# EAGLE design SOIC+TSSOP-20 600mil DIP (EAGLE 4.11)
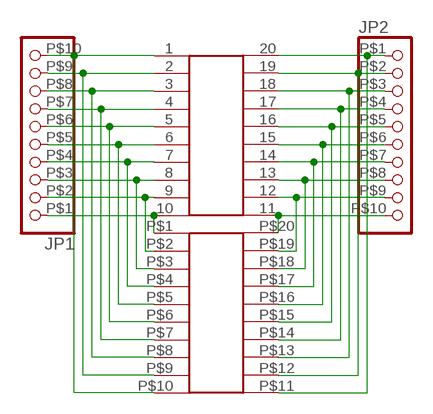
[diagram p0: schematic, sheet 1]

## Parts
JP1  PINHD-1X10THIN  [HEADER1X10]
JP2  PINHD-1X10THIN  [HEADER1X10]
U$1  SMD-20TSSOP  [TSSOP-20NM]
U$2  SMD-20SOIC  [SO-20NMW]

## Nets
N$1: JP1.P$10 U$1.1 U$2.P$10
N$2: JP1.P$9 U$1.2 U$2.P$9
N$3: JP1.P$8 U$1.3 U$2.P$8
N$4: JP1.P$7 U$1.4 U$2.P$7
N$5: JP1.P$6 U$1.5 U$2.P$6
N$6: JP1.P$5 U$1.6 U$2.P$5
N$7: JP1.P$4 U$1.7 U$2.P$4
N$8: JP1.P$3 U$1.8 U$2.P$3
N$9: JP1.P$2 U$1.9 U$2.P$2
N$10: JP1.P$1 U$1.10 U$2.P$1
N$11: JP2.P$1 U$1.20 U$2.P$11
N$12: JP2.P$2 U$1.19 U$2.P$12
N$13: JP2.P$3 U$1.18 U$2.P$13
N$14: JP2.P$5 U$1.16 U$2.P$15
N$15: JP2.P$4 U$1.17 U$2.P$14
N$16: JP2.P$6 U$1.15 U$2.P$16
N$17: JP2.P$7 U$1.14 U$2.P$17
N$18: JP2.P$8 U$1.13 U$2.P$18
N$19: JP2.P$9 U$1.12 U$2.P$19
N$20: JP2.P$10 U$1.11 U$2.P$20

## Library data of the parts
JP1 JP2 = boogie:PINHD-1X10: PIN HEADER
U$1 U$2 = boogie:SMD-20

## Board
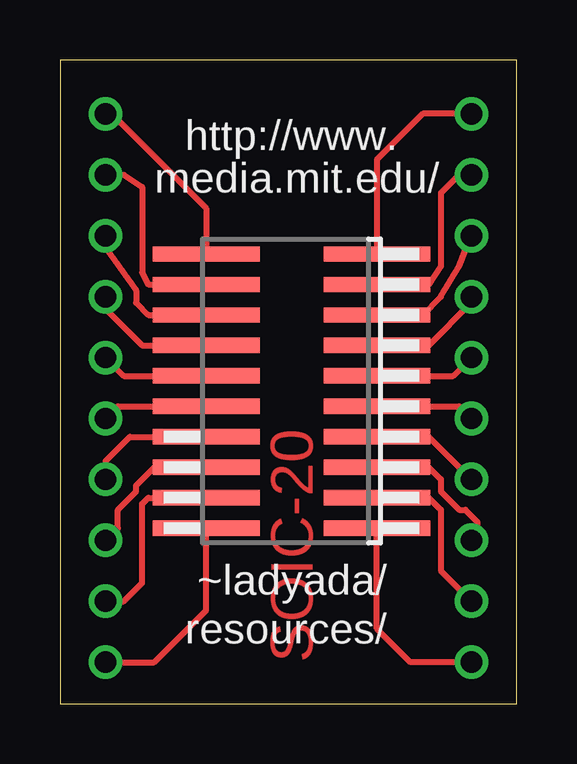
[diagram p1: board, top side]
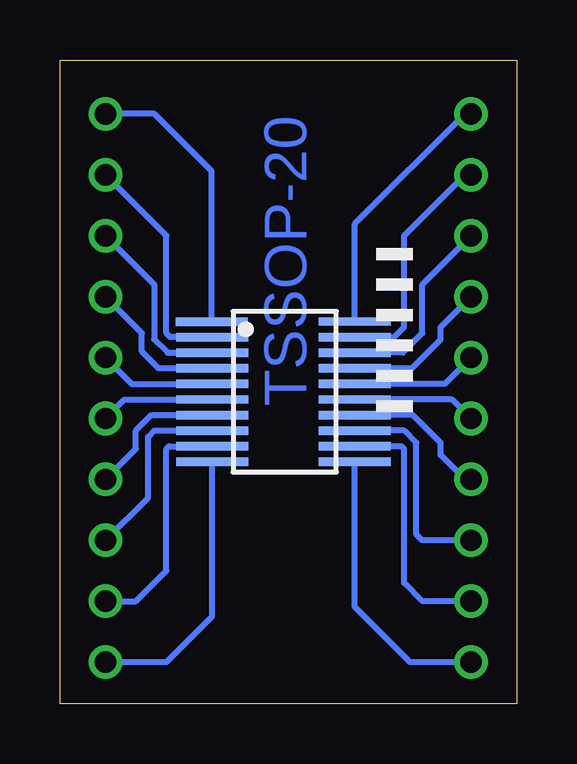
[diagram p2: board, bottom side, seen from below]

Size 19.03 x 26.85 mm. Coordinates in mm from the lower left corner, seen from the top.
Outline: 0,0 19.03,0 19.03,26.85 0,26.85 0,0
Copper layers (1*16): Top 0.035mm / dielectric 1.5mm / Bottom 0.035mm
Design rules "default": minimum track width 10mil, minimum drill 24mil, track to track 10mil, track to pad 10mil, pad to pad 10mil, via to via 10mil, smd to smd 8mil, copper to edge 40mil, drill to drill 8mil, minimum pad ring 10mil, minimum via ring 8mil, stop-mask expansion 4mil, vias tented up to drill 0mil, thermal gap 10mil

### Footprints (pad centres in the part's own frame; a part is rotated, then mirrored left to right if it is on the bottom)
HEADER1X10 = drill 0.889 round: P$1 11.43,0; P$2 8.89,0; P$3 6.35,0; P$4 3.81,0; P$5 1.27,0; P$6 -1.27,0; P$7 -3.81,0; P$8 -6.35,0; P$9 -8.89,0; P$10 -11.43,0
TSSOP-20NM = smd 0.35 x 3: 1 -1.745,-3.193; 2 -1.105,-3.169; 3 -0.455,-3.169; 4 0.195,-3.169; 5 0.845,-3.169; 6 1.495,-3.169; 7 2.145,-3.169; 8 2.795,-3.169; 9 3.445,-3.169; 10 4.095,-3.169; 11 4.095,2.781; 12 3.445,2.781; 13 2.795,2.781; 14 2.145,2.781; 15 1.495,2.781; 16 0.845,2.781; 17 0.195,2.781; 18 -0.455,2.781; 19 -1.105,2.781; 20 -1.755,2.781
SO-20NMW = smd 0.635 x 4.445: P$1 -4.318,-3.683; P$2 -3.048,-3.683; P$3 -1.778,-3.683; P$4 -0.508,-3.683; P$5 0.762,-3.683; P$6 2.032,-3.683; P$7 3.302,-3.683; P$8 4.572,-3.683; P$9 5.842,-3.683; P$10 7.112,-3.683; P$11 7.112,3.429; P$12 5.842,3.429; P$13 4.572,3.429; P$14 3.302,3.429; P$15 2.032,3.429; P$16 0.762,3.429; P$17 -0.508,3.429; P$18 -1.778,3.429; P$19 -3.048,3.429; P$20 -4.318,3.429

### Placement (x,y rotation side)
JP1  17.14,13.17 270 top
JP2  1.9,13.17 90 top
U$1  9.52,14.19 270 bottom
U$2  9.52,11.65 90 top

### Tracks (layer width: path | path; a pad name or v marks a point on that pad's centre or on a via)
N$1
  Top 0.254: U$2.P$10 13.2,22.7 15.11,24.6 JP1.P$10
  Bottom 0.254: U$1.1 12.71,22.2 15.11,24.6 JP1.P$10
N$2
  Top 0.254: U$2.P$9 15.36,17.49 15.87,18.25 15.87,21.3 16.63,22.06 JP1.P$9
  Bottom 0.254: U$1.2 14.43,15.29 14.6,15.46 14.6,19.52 JP1.P$9
N$3
  Top 0.254: U$2.P$8 15.11,16.22 15.87,16.98 16.63,18.25 JP1.P$8
  Bottom 0.254: U$1.3 14.55,14.64 15.11,15.2 15.11,17.49 JP1.P$8
N$4
  Top 0.254: JP1.P$7 17.14,16.73 15.36,14.95 U$2.P$7
  Bottom 0.254: U$1.4 14.91,13.99 15.62,14.69 15.62,15.46 JP1.P$7
N$5
  Top 0.254: U$2.P$6 16.38,13.68 JP1.P$6
  Bottom 0.254: U$1.5 16.04,13.34 JP1.P$6
N$6
  Top 0.254: U$2.P$5 16.63,12.41 JP1.P$5
  Bottom 0.254: U$1.6 16.35,12.69 JP1.P$5
N$7
  Top 0.254: U$2.P$4 15.36,11.14 JP1.P$4
  Bottom 0.254: U$1.7 15.22,12.04 15.87,11.39 15.87,10.63 JP1.P$4
N$8
  Top 0.254: U$2.P$3 15.36,9.87 15.87,9.36 15.87,8.85 16.63,8.09 16.89,8.09 17.39,7.58 17.39,7.33 17.14,7.07 JP1.P$3
  Bottom 0.254: U$1.8 15.11,11.39 15.36,11.14 15.36,8.6 JP1.P$3
N$9
  Top 0.254: U$2.P$2 15.36,8.6 15.87,8.09 15.87,5.55 JP1.P$2
  Bottom 0.254: U$1.9 14.49,10.74 14.6,10.63 14.6,5.55 15.87,4.28 16.89,4.28 17.14,4.53 JP1.P$2
N$10
  Top 0.254: U$2.P$1 13.2,3.14 14.6,1.74 JP1.P$1
  Bottom 0.254: U$1.10 12.69,3.65 14.6,1.74 JP1.P$1
N$11
  Top 0.254: JP2.P$1 2.15,24.6 6.09,20.66 U$2.P$11
  Bottom 0.254: U$1.20 6.74,20.02 2.15,24.6 JP2.P$1
N$12
  Top 0.254: U$2.P$12 3.68,17.49 3.42,18 3.42,21.55 2.66,22.06 JP2.P$2
  Bottom 0.254: U$1.19 5.11,15.29 4.69,15.71 4.69,19.52 2.15,22.06 JP2.P$2
N$13
  Top 0.254: U$2.P$13 3.68,16.22 3.17,16.73 3.17,17.23 1.9,19.01 JP2.P$3 1.9,19.77
  Bottom 0.254: U$1.18 4.75,14.64 3.93,15.46 3.93,17.49 JP2.P$3
N$14
  Top 0.254: U$2.P$15 2.66,13.68 JP2.P$5
  Bottom 0.254: U$1.16 3,13.34 JP2.P$5
N$15
  Top 0.254: JP2.P$4 1.9,16.47 3.42,14.95 U$2.P$14
  Bottom 0.254: U$1.17 4.38,13.99 3.17,15.2 3.17,15.71 JP2.P$4
N$16
  Top 0.254: U$2.P$16 2.41,12.41 JP2.P$6
  Bottom 0.254: U$1.15 2.69,12.69 JP2.P$6
N$17
  Top 0.254: U$2.P$17 2.92,11.14 1.9,10.12 JP2.P$7
  Bottom 0.254: U$1.14 4.33,12.04 3.17,10.88 3.17,10.38 2.15,9.36 JP2.P$7
N$18
  Top 0.254: U$2.P$18 3.93,9.87 3.17,9.11 3.17,8.85 2.41,8.09 2.41,7.33 JP2.P$8
  Bottom 0.254: U$1.13 4.69,11.39 4.19,10.88 4.19,7.07 3.93,6.82 JP2.P$8
N$19
  Top 0.254: U$2.P$19 3.68,8.6 3.42,8.34 3.42,5.04 2.66,4.28 JP2.P$9
  Bottom 0.254: U$1.12 4.81,10.74 4.69,10.63 4.69,5.04 3.93,4.28 JP2.P$9 1.65,4.28
N$20
  Top 0.254: U$2.P$20 6.09,3.9 3.93,1.74 JP2.P$10 1.65,1.74
  Bottom 0.254: U$1.11 6.74,4.04 4.44,1.74 JP2.P$10

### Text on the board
Top: SOIC-20
Bottom: TSSOP-20
tPlace: http://www. | media.mit.edu/ | ~ladyada/ | resources/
